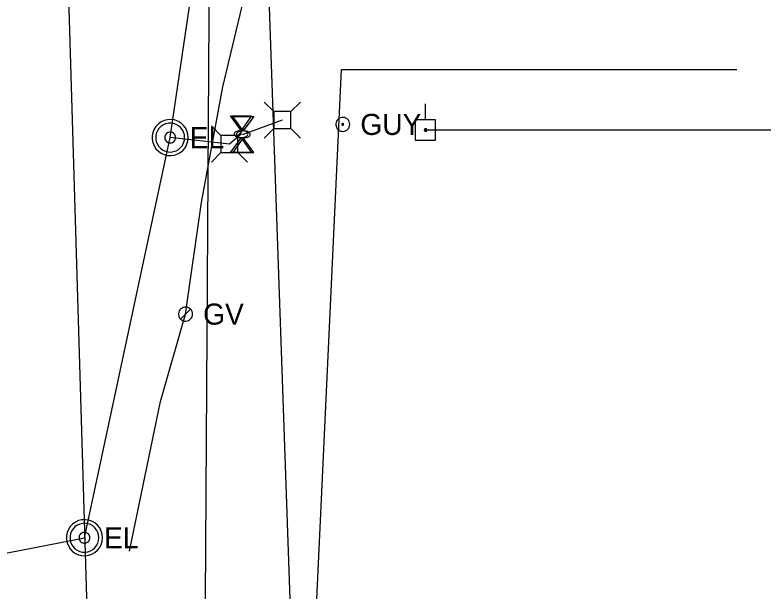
# Model space of a CAD drawing. Extents: x 596028 to 606371, y 330010 to 403088.
# Drawn here: x 605009.9 to 605146.4, y 331475.9 to 331581 of the extents above; entities that cross this region are included whole.
import ezdxf

# ---------------------------------------------------------------- set-up
doc = ezdxf.new("R2010")
doc.units = 0
for name, color, linetype in [('E_UTL_E', 7, 'Continuous'), ('E_UTL_E_Bold', 7, 'Continuous'), ('E_UTL_E_UG', 7, 'Continuous'), ('E_UTL_EGuyWire', 7, 'Continuous'), ('E_UTL_EPowerPole', 7, 'Continuous'), ('E_UTL_G', 7, 'Continuous'), ('E_UTL_G_UG', 7, 'Continuous'), ('E_UTL_Overhead', 7, 'Continuous'), ('E_UTL_SAN_UG', 7, 'Continuous'), ('E_UTL_SAN_UG_MMSD', 7, 'Continuous'), ('E_UTL_W_UG', 7, 'Continuous')]:
    doc.layers.add(name, color=color, linetype=linetype)

msp = doc.modelspace()

# ---------------------------------------------------------------- linework, layer by layer
at = {"layer": 'E_UTL_E'}
for points in [[(605057.12, 331563.38), (605055.37, 331565.13)], [(605060.22, 331563.38), (605061.97, 331565.13)], [(605060.22, 331563.38), (605057.12, 331563.38)], [(605057.12, 331563.38), (605057.12, 331560.28)], [(605060.22, 331560.28), (605060.22, 331563.38)], [(605041.5, 331558.64), (605041.44, 331559.26), (605041.27, 331559.86), (605040.98, 331560.42), (605040.59, 331560.92), (605040.12, 331561.33), (605039.57, 331561.64), (605038.98, 331561.85), (605038.36, 331561.93), (605037.73, 331561.9), (605037.12, 331561.76), (605036.55, 331561.5), (605036.04, 331561.13), (605035.61, 331560.68), (605035.27, 331560.15), (605035.04, 331559.57), (605034.92, 331558.95), (605034.92, 331558.32), (605035.04, 331557.71), (605035.27, 331557.13), (605035.61, 331556.6), (605036.04, 331556.14), (605036.55, 331555.78), (605037.12, 331555.52), (605037.73, 331555.37), (605038.36, 331555.34), (605038.98, 331555.43), (605039.57, 331555.64), (605040.12, 331555.95), (605040.59, 331556.36), (605040.98, 331556.85), (605041.27, 331557.41), (605041.44, 331558.01), (605041.5, 331558.64)], [(605041.5, 331558.64), (605041.44, 331559.26), (605041.27, 331559.86), (605040.98, 331560.42), (605040.59, 331560.92), (605040.12, 331561.33), (605039.57, 331561.64), (605038.98, 331561.85), (605038.36, 331561.93), (605037.73, 331561.9), (605037.12, 331561.76), (605036.55, 331561.5), (605036.04, 331561.13), (605035.61, 331560.68), (605035.27, 331560.15), (605035.04, 331559.57), (605034.92, 331558.95), (605034.92, 331558.32), (605035.04, 331557.71), (605035.27, 331557.13), (605035.61, 331556.6), (605036.04, 331556.14), (605036.55, 331555.78), (605037.12, 331555.52), (605037.73, 331555.37), (605038.36, 331555.34), (605038.98, 331555.43), (605039.57, 331555.64), (605040.12, 331555.95), (605040.59, 331556.36), (605040.98, 331556.85), (605041.27, 331557.41), (605041.44, 331558.01), (605041.5, 331558.64)], [(605040.84, 331558.64), (605040.79, 331559.14), (605040.65, 331559.62), (605040.42, 331560.07), (605040.11, 331560.46), (605039.73, 331560.79), (605039.3, 331561.04), (605038.82, 331561.2), (605038.33, 331561.28), (605037.83, 331561.25), (605037.34, 331561.13), (605036.88, 331560.92), (605036.47, 331560.63), (605036.13, 331560.27), (605035.86, 331559.85), (605035.67, 331559.38), (605035.57, 331558.89), (605035.57, 331558.39), (605035.67, 331557.89), (605035.86, 331557.43), (605036.13, 331557.01), (605036.47, 331556.64), (605036.88, 331556.35), (605037.34, 331556.14), (605037.83, 331556.02), (605038.33, 331556), (605038.82, 331556.07), (605039.3, 331556.24), (605039.73, 331556.49), (605040.11, 331556.82), (605040.42, 331557.21), (605040.65, 331557.66), (605040.79, 331558.14), (605040.84, 331558.64)], [(605040.84, 331558.64), (605040.79, 331559.14), (605040.65, 331559.62), (605040.42, 331560.07), (605040.11, 331560.46), (605039.73, 331560.79), (605039.3, 331561.04), (605038.82, 331561.2), (605038.33, 331561.28), (605037.83, 331561.25), (605037.34, 331561.13), (605036.88, 331560.92), (605036.47, 331560.63), (605036.13, 331560.27), (605035.86, 331559.85), (605035.67, 331559.38), (605035.57, 331558.89), (605035.57, 331558.39), (605035.67, 331557.89), (605035.86, 331557.43), (605036.13, 331557.01), (605036.47, 331556.64), (605036.88, 331556.35), (605037.34, 331556.14), (605037.83, 331556.02), (605038.33, 331556), (605038.82, 331556.07), (605039.3, 331556.24), (605039.73, 331556.49), (605040.11, 331556.82), (605040.42, 331557.21), (605040.65, 331557.66), (605040.79, 331558.14), (605040.84, 331558.64)], [(605047.47, 331559.01), (605045.72, 331560.76)], [(605050.57, 331559.01), (605052.32, 331560.76)], [(605057.12, 331560.28), (605055.37, 331558.53)], [(605057.12, 331560.28), (605060.22, 331560.28)], [(605060.22, 331560.28), (605061.97, 331558.53)], [(605039.19, 331558.64), (605039.17, 331558.83), (605039.12, 331559.01), (605039.03, 331559.17), (605038.92, 331559.32), (605038.78, 331559.44), (605038.61, 331559.54), (605038.44, 331559.6), (605038.25, 331559.63), (605038.06, 331559.62), (605037.88, 331559.57), (605037.71, 331559.5), (605037.55, 331559.39), (605037.42, 331559.25), (605037.32, 331559.09), (605037.25, 331558.92), (605037.22, 331558.73), (605037.22, 331558.54), (605037.25, 331558.36), (605037.32, 331558.18), (605037.42, 331558.03), (605037.55, 331557.89), (605037.71, 331557.78), (605037.88, 331557.7), (605038.06, 331557.66), (605038.25, 331557.65), (605038.44, 331557.68), (605038.61, 331557.74), (605038.78, 331557.83), (605038.92, 331557.95), (605039.03, 331558.1), (605039.12, 331558.27), (605039.17, 331558.45), (605039.19, 331558.64)], [(605039.19, 331558.64), (605039.17, 331558.83), (605039.12, 331559.01), (605039.03, 331559.17), (605038.92, 331559.32), (605038.78, 331559.44), (605038.61, 331559.54), (605038.44, 331559.6), (605038.25, 331559.63), (605038.06, 331559.62), (605037.88, 331559.57), (605037.71, 331559.5), (605037.55, 331559.39), (605037.42, 331559.25), (605037.32, 331559.09), (605037.25, 331558.92), (605037.22, 331558.73), (605037.22, 331558.54), (605037.25, 331558.36), (605037.32, 331558.18), (605037.42, 331558.03), (605037.55, 331557.89), (605037.71, 331557.78), (605037.88, 331557.7), (605038.06, 331557.66), (605038.25, 331557.65), (605038.44, 331557.68), (605038.61, 331557.74), (605038.78, 331557.83), (605038.92, 331557.95), (605039.03, 331558.1), (605039.12, 331558.27), (605039.17, 331558.45), (605039.19, 331558.64)], [(605050.57, 331559.01), (605047.47, 331559.01)], [(605047.47, 331559.01), (605047.47, 331555.91)], [(605050.57, 331555.91), (605050.57, 331559.01)], [(605047.47, 331555.91), (605045.72, 331554.16)], [(605047.47, 331555.91), (605050.57, 331555.91)], [(605050.57, 331555.91), (605052.32, 331554.16)], [(605025.85, 331485.6), (605025.79, 331486.22), (605025.62, 331486.82), (605025.33, 331487.38), (605024.94, 331487.88), (605024.47, 331488.29), (605023.92, 331488.6), (605023.33, 331488.81), (605022.71, 331488.89), (605022.08, 331488.86), (605021.47, 331488.72), (605020.9, 331488.46), (605020.39, 331488.09), (605019.96, 331487.64), (605019.62, 331487.11), (605019.39, 331486.53), (605019.27, 331485.91), (605019.27, 331485.28), (605019.39, 331484.67), (605019.62, 331484.09), (605019.96, 331483.56), (605020.39, 331483.1), (605020.9, 331482.74), (605021.47, 331482.48), (605022.08, 331482.33), (605022.71, 331482.3), (605023.33, 331482.39), (605023.92, 331482.6), (605024.47, 331482.91), (605024.94, 331483.32), (605025.33, 331483.81), (605025.62, 331484.37), (605025.79, 331484.97), (605025.85, 331485.6)], [(605025.85, 331485.6), (605025.79, 331486.22), (605025.62, 331486.82), (605025.33, 331487.38), (605024.94, 331487.88), (605024.47, 331488.29), (605023.92, 331488.6), (605023.33, 331488.81), (605022.71, 331488.89), (605022.08, 331488.86), (605021.47, 331488.72), (605020.9, 331488.46), (605020.39, 331488.09), (605019.96, 331487.64), (605019.62, 331487.11), (605019.39, 331486.53), (605019.27, 331485.91), (605019.27, 331485.28), (605019.39, 331484.67), (605019.62, 331484.09), (605019.96, 331483.56), (605020.39, 331483.1), (605020.9, 331482.74), (605021.47, 331482.48), (605022.08, 331482.33), (605022.71, 331482.3), (605023.33, 331482.39), (605023.92, 331482.6), (605024.47, 331482.91), (605024.94, 331483.32), (605025.33, 331483.81), (605025.62, 331484.37), (605025.79, 331484.97), (605025.85, 331485.6)], [(605025.19, 331485.6), (605025.14, 331486.1), (605025, 331486.58), (605024.77, 331487.03), (605024.46, 331487.42), (605024.08, 331487.75), (605023.65, 331488), (605023.17, 331488.16), (605022.68, 331488.24), (605022.18, 331488.21), (605021.69, 331488.09), (605021.23, 331487.88), (605020.82, 331487.59), (605020.48, 331487.23), (605020.21, 331486.81), (605020.02, 331486.34), (605019.92, 331485.85), (605019.92, 331485.35), (605020.02, 331484.85), (605020.21, 331484.39), (605020.48, 331483.97), (605020.82, 331483.6), (605021.23, 331483.31), (605021.69, 331483.1), (605022.18, 331482.99), (605022.68, 331482.96), (605023.17, 331483.03), (605023.65, 331483.2), (605024.08, 331483.45), (605024.46, 331483.78), (605024.77, 331484.17), (605025, 331484.62), (605025.14, 331485.1), (605025.19, 331485.6)], [(605025.19, 331485.6), (605025.14, 331486.1), (605025, 331486.58), (605024.77, 331487.03), (605024.46, 331487.42), (605024.08, 331487.75), (605023.65, 331488), (605023.17, 331488.16), (605022.68, 331488.24), (605022.18, 331488.21), (605021.69, 331488.09), (605021.23, 331487.88), (605020.82, 331487.59), (605020.48, 331487.23), (605020.21, 331486.81), (605020.02, 331486.34), (605019.92, 331485.85), (605019.92, 331485.35), (605020.02, 331484.85), (605020.21, 331484.39), (605020.48, 331483.97), (605020.82, 331483.6), (605021.23, 331483.31), (605021.69, 331483.1), (605022.18, 331482.99), (605022.68, 331482.96), (605023.17, 331483.03), (605023.65, 331483.2), (605024.08, 331483.45), (605024.46, 331483.78), (605024.77, 331484.17), (605025, 331484.62), (605025.14, 331485.1), (605025.19, 331485.6)], [(605023.54, 331485.6), (605023.52, 331485.79), (605023.47, 331485.97), (605023.38, 331486.13), (605023.27, 331486.28), (605023.13, 331486.4), (605022.96, 331486.5), (605022.79, 331486.56), (605022.6, 331486.59), (605022.41, 331486.58), (605022.23, 331486.53), (605022.06, 331486.46), (605021.9, 331486.35), (605021.77, 331486.21), (605021.67, 331486.05), (605021.6, 331485.88), (605021.57, 331485.69), (605021.57, 331485.5), (605021.6, 331485.32), (605021.67, 331485.14), (605021.77, 331484.99), (605021.9, 331484.85), (605022.06, 331484.74), (605022.23, 331484.66), (605022.41, 331484.62), (605022.6, 331484.61), (605022.79, 331484.64), (605022.96, 331484.7), (605023.13, 331484.79), (605023.27, 331484.91), (605023.38, 331485.06), (605023.47, 331485.23), (605023.52, 331485.41), (605023.54, 331485.6)], [(605023.54, 331485.6), (605023.52, 331485.79), (605023.47, 331485.97), (605023.38, 331486.13), (605023.27, 331486.28), (605023.13, 331486.4), (605022.96, 331486.5), (605022.79, 331486.56), (605022.6, 331486.59), (605022.41, 331486.58), (605022.23, 331486.53), (605022.06, 331486.46), (605021.9, 331486.35), (605021.77, 331486.21), (605021.67, 331486.05), (605021.6, 331485.88), (605021.57, 331485.69), (605021.57, 331485.5), (605021.6, 331485.32), (605021.67, 331485.14), (605021.77, 331484.99), (605021.9, 331484.85), (605022.06, 331484.74), (605022.23, 331484.66), (605022.41, 331484.62), (605022.6, 331484.61), (605022.79, 331484.64), (605022.96, 331484.7), (605023.13, 331484.79), (605023.27, 331484.91), (605023.38, 331485.06), (605023.47, 331485.23), (605023.52, 331485.41), (605023.54, 331485.6)]]:
    msp.add_lwpolyline(points, dxfattribs=at)
at = {"layer": 'E_UTL_E_Bold'}
for points in [[(605049.24, 331562.58), (605053.06, 331562.58)], [(605051.15, 331559.91), (605049.24, 331562.58)], [(605049.64, 331562.51), (605053.46, 331562.51)], [(605051.55, 331559.84), (605049.64, 331562.51)], [(605053.06, 331562.58), (605051.15, 331559.91)], [(605053.46, 331562.51), (605051.55, 331559.84)], [(605052.42, 331559.28), (605052.4, 331559.4), (605052.33, 331559.51), (605052.22, 331559.62), (605052.07, 331559.72), (605051.89, 331559.79), (605051.68, 331559.85), (605051.45, 331559.89), (605051.21, 331559.91), (605050.97, 331559.91), (605050.73, 331559.88), (605050.51, 331559.83), (605050.32, 331559.76), (605050.15, 331559.67), (605050.02, 331559.57), (605049.93, 331559.46), (605049.89, 331559.34), (605049.89, 331559.22), (605049.93, 331559.1), (605050.02, 331558.99), (605050.15, 331558.88), (605050.32, 331558.8), (605050.51, 331558.73), (605050.73, 331558.68), (605050.97, 331558.65), (605051.21, 331558.64), (605051.45, 331558.66), (605051.68, 331558.7), (605051.89, 331558.76), (605052.07, 331558.84), (605052.22, 331558.93), (605052.33, 331559.04), (605052.4, 331559.16), (605052.42, 331559.28)], [(605052.82, 331559.21), (605052.8, 331559.33), (605052.73, 331559.44), (605052.62, 331559.55), (605052.47, 331559.65), (605052.29, 331559.72), (605052.08, 331559.78), (605051.85, 331559.82), (605051.61, 331559.84), (605051.37, 331559.84), (605051.13, 331559.81), (605050.91, 331559.76), (605050.72, 331559.69), (605050.55, 331559.6), (605050.42, 331559.5), (605050.33, 331559.39), (605050.29, 331559.27), (605050.29, 331559.15), (605050.33, 331559.03), (605050.42, 331558.92), (605050.55, 331558.81), (605050.72, 331558.73), (605050.91, 331558.66), (605051.13, 331558.61), (605051.37, 331558.58), (605051.61, 331558.57), (605051.85, 331558.59), (605052.08, 331558.63), (605052.29, 331558.69), (605052.47, 331558.77), (605052.62, 331558.86), (605052.73, 331558.97), (605052.8, 331559.09), (605052.82, 331559.21)], [(605051.15, 331558.64), (605049.24, 331555.98)], [(605051.55, 331558.57), (605049.64, 331555.91)], [(605053.06, 331555.98), (605051.15, 331558.64)], [(605053.46, 331555.91), (605051.55, 331558.57)], [(605049.24, 331555.98), (605053.06, 331555.98)], [(605049.64, 331555.91), (605053.46, 331555.91)]]:
    msp.add_lwpolyline(points, dxfattribs=at)
at = {"layer": 'E_UTL_E_UG'}
for points in [[(605038.2, 331558.64), (605053.97, 331665.58), (605054.16, 331675.48), (605057.33, 331710.76), (605063.33, 331779.39), (605064.89, 331811.56), (605066.7, 331922.92), (605066.28, 331973.16), (605065.35, 332014.58), (605064.76, 332065.68), (605063.4, 332175.3), (605062.74, 332212.21)], [(604870.57, 331033.54), (605033.08, 331252.35), (605033.08, 331392.8), (605061.51, 331399.86), (605069.48, 331571.07), (605141.68, 331571.07)], [(605058.67, 331561.83), (605051.55, 331559.21), (605051.15, 331559.28), (605049.02, 331557.46), (605038.2, 331558.64)], [(604983.14, 331477.94), (605022.55, 331485.6), (605038.2, 331558.64)]]:
    msp.add_lwpolyline(points, dxfattribs=at)
at = {"layer": 'E_UTL_EGuyWire'}
for points in [[(605070.99, 331561.05), (605070.97, 331561.29), (605070.9, 331561.52), (605070.79, 331561.74), (605070.64, 331561.93), (605070.45, 331562.09), (605070.24, 331562.21), (605070.01, 331562.29), (605069.77, 331562.33), (605069.53, 331562.32), (605069.29, 331562.26), (605069.07, 331562.16), (605068.87, 331562.02), (605068.7, 331561.84), (605068.57, 331561.63), (605068.48, 331561.41), (605068.43, 331561.17), (605068.43, 331560.92), (605068.48, 331560.69), (605068.57, 331560.46), (605068.7, 331560.25), (605068.87, 331560.08), (605069.07, 331559.94), (605069.29, 331559.83), (605069.53, 331559.78), (605069.77, 331559.76), (605070.01, 331559.8), (605070.24, 331559.88), (605070.45, 331560), (605070.64, 331560.16), (605070.79, 331560.35), (605070.9, 331560.57), (605070.97, 331560.8), (605070.99, 331561.05)], [(605069.87, 331561.05), (605069.87, 331561.08), (605069.86, 331561.11), (605069.84, 331561.13), (605069.83, 331561.16), (605069.8, 331561.18), (605069.78, 331561.19), (605069.75, 331561.2), (605069.72, 331561.21), (605069.69, 331561.21), (605069.66, 331561.2), (605069.63, 331561.19), (605069.6, 331561.17), (605069.58, 331561.15), (605069.57, 331561.12), (605069.56, 331561.09), (605069.55, 331561.06), (605069.55, 331561.03), (605069.56, 331561), (605069.57, 331560.97), (605069.58, 331560.95), (605069.6, 331560.93), (605069.63, 331560.91), (605069.66, 331560.9), (605069.69, 331560.89), (605069.72, 331560.89), (605069.75, 331560.89), (605069.78, 331560.9), (605069.8, 331560.92), (605069.83, 331560.94), (605069.84, 331560.96), (605069.86, 331560.99), (605069.87, 331561.02), (605069.87, 331561.05)]]:
    msp.add_lwpolyline(points, dxfattribs=at)
at = {"layer": 'E_UTL_EPowerPole'}
for points in [[(605084.81, 331561.86), (605084.81, 331564.77)], [(605086.65, 331561.86), (605082.96, 331561.86)], [(605082.96, 331561.86), (605082.96, 331558.17)], [(605086.65, 331558.17), (605086.65, 331561.86)], [(605085.08, 331560.02), (605085.07, 331560.06), (605085.06, 331560.11), (605085.04, 331560.15), (605085.01, 331560.18), (605084.98, 331560.21), (605084.94, 331560.23), (605084.9, 331560.25), (605084.85, 331560.25), (605084.81, 331560.25), (605084.76, 331560.24), (605084.72, 331560.22), (605084.68, 331560.2), (605084.65, 331560.16), (605084.63, 331560.13), (605084.61, 331560.08), (605084.6, 331560.04), (605084.6, 331559.99), (605084.61, 331559.95), (605084.63, 331559.91), (605084.65, 331559.87), (605084.68, 331559.84), (605084.72, 331559.81), (605084.76, 331559.79), (605084.81, 331559.78), (605084.85, 331559.78), (605084.9, 331559.78), (605084.94, 331559.8), (605084.98, 331559.82), (605085.01, 331559.85), (605085.04, 331559.89), (605085.06, 331559.93), (605085.07, 331559.97), (605085.08, 331560.02)], [(605082.96, 331558.17), (605086.65, 331558.17)]]:
    msp.add_lwpolyline(points, dxfattribs=at)
at = {"layer": 'E_UTL_G'}
for points in [[(605042.28, 331526.42), (605042.26, 331526.66), (605042.19, 331526.89), (605042.08, 331527.11), (605041.93, 331527.3), (605041.74, 331527.46), (605041.53, 331527.58), (605041.3, 331527.66), (605041.06, 331527.7), (605040.82, 331527.69), (605040.58, 331527.63), (605040.36, 331527.53), (605040.16, 331527.39), (605039.99, 331527.21), (605039.86, 331527.01), (605039.77, 331526.78), (605039.72, 331526.54), (605039.72, 331526.29), (605039.77, 331526.06), (605039.86, 331525.83), (605039.99, 331525.62), (605040.16, 331525.45), (605040.36, 331525.31), (605040.58, 331525.2), (605040.82, 331525.15), (605041.06, 331525.14), (605041.3, 331525.17), (605041.53, 331525.25), (605041.74, 331525.37), (605041.93, 331525.53), (605042.08, 331525.72), (605042.19, 331525.94), (605042.26, 331526.17), (605042.28, 331526.42)], [(605040.09, 331525.51), (605041.91, 331527.32)]]:
    msp.add_lwpolyline(points, dxfattribs=at)
at = {"layer": 'E_UTL_G_UG'}
msp.add_lwpolyline([(605030.78, 331483.16), (605036.41, 331510.46), (605041, 331526.42), (605043.91, 331546.77), (605047.79, 331567.91), (605052.35, 331587.01), (605059.28, 331633.75), (605064.76, 331677.5), (605068.49, 331707.7), (605074.22, 331781.45), (605075.46, 331809.71), (605078.06, 331885.79), (605077.96, 331921.74), (605077.56, 331972.3), (605077.08, 332012.55), (605076.17, 332068.78), (605075.45, 332099.34), (605075.08, 332165.21), (605074.66, 332210.44), (605074.75, 332235.8)], dxfattribs=at)
at = {"layer": 'E_UTL_Overhead'}
msp.add_lwpolyline([(605084.84, 331560.02), (605283.92, 331560.02)], dxfattribs=at)
at = {"layer": 'E_UTL_SAN_UG'}
msp.add_line((605060.52, 331462.84), (605048.95, 331795.33), dxfattribs=at)
at = {"layer": 'E_UTL_SAN_UG_MMSD'}
msp.add_line((605023.68, 331451.52), (605012.41, 331824.88), dxfattribs=at)
at = {"layer": 'E_UTL_W_UG'}
msp.add_lwpolyline([(604662.85, 330776.78), (604719.99, 330861.17), (604771.51, 330900.13), (604792.62, 330926.22), (604804.59, 330947.13), (605054.68, 331381.7), (605055.13, 331442.45), (605044.65, 331474.36), (605047.01, 331851.63), (605038.36, 332278.66), (605035.8, 332410.28), (605072.23, 332411.32), (605076.98, 332411.12), (605079.88, 332411.16)], dxfattribs=at)

# ---------------------------------------------------------------- texts
at = {"layer": 'E_UTL_E'}
for p in [(605041.77, 331556.69), (605041.77, 331556.69), (605026.12, 331483.65), (605026.12, 331483.65)]:
    msp.add_text('EL', height=3.849, dxfattribs=at).set_placement(p)
at = {"layer": 'E_UTL_EGuyWire'}
msp.add_text('GUY', height=3.85, dxfattribs=at).set_placement((605072.92, 331559.12))
at = {"layer": 'E_UTL_G'}
msp.add_text('GV', height=3.85, dxfattribs=at).set_placement((605044.21, 331524.49))

doc.saveas('drawing.dxf')
